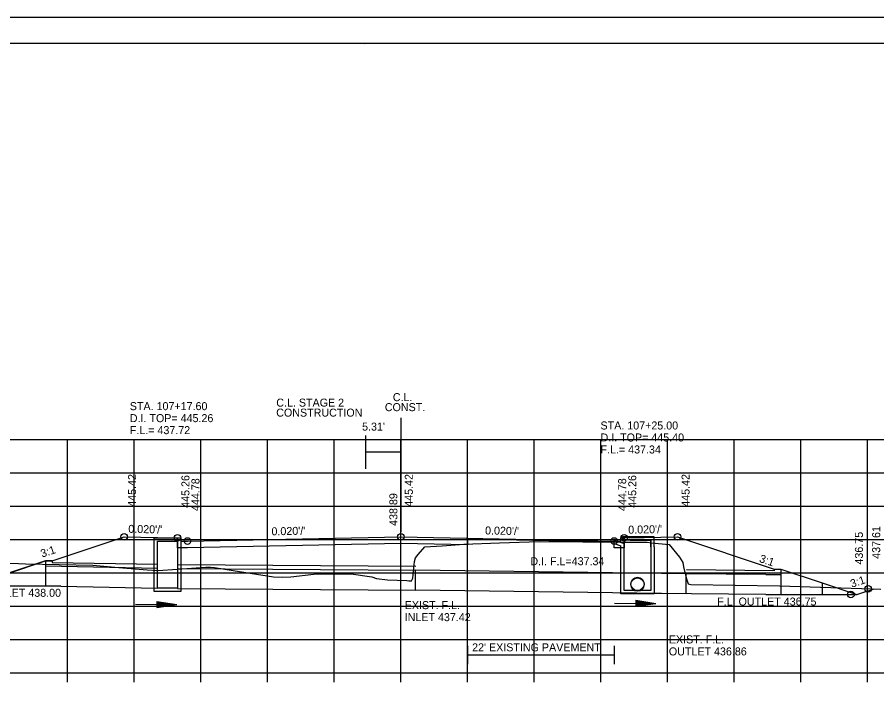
# Model space of a CAD drawing. Extents: x 1538688 to 1540766, y 656250 to 671912.
# Drawn here: x 1538800.6 to 1538929.6, y 657517.5 to 657617.9 of the extents above; entities that cross this region are included whole.
import ezdxf

# ---------------------------------------------------------------- set-up
doc = ezdxf.new("R2010")
doc.units = 0
for name, color, linetype in [('15', 7, 'Continuous'), ('18', 7, 'Continuous'), ('20', 7, 'Continuous'), ('22', 7, 'Continuous'), ('26', 7, 'Continuous'), ('39', 7, 'Continuous'), ('40', 7, 'Continuous'), ('41', 7, 'Continuous'), ('42', 7, 'Continuous'), ('7', 7, 'Continuous'), ('Borings', 7, 'Continuous'), ('Default', 7, 'Continuous'), ('RipRap', 7, 'Continuous'), ('Wall Heights', 7, 'Continuous')]:
    doc.layers.add(name, color=color, linetype=linetype)

msp = doc.modelspace()

# ---------------------------------------------------------------- linework, layer by layer
at = {"layer": '15'}
for p, q in [((1538821.58, 657530.29), (1538821.57, 657529.39)), ((1538821.57, 657530.06), (1538823.06, 657529.82)), ((1538821.58, 657530.29), (1538824.57, 657529.81)), ((1538821.58, 657530.21), (1538824.07, 657529.82)), ((1538821.58, 657530.13), (1538823.56, 657529.82)), ((1538893.42, 657530.48), (1538893.41, 657529.58)), ((1538893.42, 657530.48), (1538896.42, 657530)), ((1538893.42, 657530.4), (1538895.92, 657530.01)), ((1538893.42, 657530.33), (1538895.4, 657530.01)), ((1538893.42, 657530.25), (1538894.9, 657530.02)), ((1538893.42, 657530.17), (1538894.39, 657530.02)), ((1538893.42, 657530.1), (1538893.89, 657530.02)), ((1538821.57, 657529.98), (1538822.55, 657529.83)), ((1538821.57, 657529.91), (1538822.05, 657529.83)), ((1538821.57, 657529.69), (1538822.55, 657529.83)), ((1538821.57, 657529.77), (1538822.05, 657529.83)), ((1538821.57, 657529.54), (1538823.56, 657529.82)), ((1538821.57, 657529.46), (1538824.07, 657529.82)), ((1538821.57, 657529.61), (1538823.06, 657529.82)), ((1538821.57, 657529.39), (1538824.57, 657529.81)), ((1538893.41, 657529.73), (1538895.4, 657530.01)), ((1538893.41, 657529.65), (1538895.92, 657530.01)), ((1538893.41, 657529.58), (1538896.42, 657530)), ((1538893.42, 657529.88), (1538894.39, 657530.02)), ((1538893.42, 657529.8), (1538894.9, 657530.02)), ((1538893.42, 657529.96), (1538893.89, 657530.02))]:
    msp.add_line(p, q, dxfattribs=at)
at = {"layer": '18'}
msp.add_lwpolyline([(1538790.3, 657536.35), (1538800.84, 657535.98), (1538801.91, 657535.93), (1538811.97, 657535.71), (1538815.3, 657535.43), (1538820.11, 657535.02), (1538821.8, 657534.92), (1538827.5, 657535.34), (1538828.92, 657535.41), (1538829.61, 657535.42), (1538830.23, 657535.36), (1538833.02, 657534.94), (1538839.1, 657533.96), (1538840.37, 657533.92), (1538841.7, 657534), (1538845.15, 657534.4), (1538850.75, 657534.43), (1538853.83, 657533.98), (1538854.54, 657533.72), (1538856.17, 657533.55), (1538859.09, 657533.42), (1538859.4, 657533.38), (1538859.76, 657533.39), (1538859.96, 657533.77), (1538860.25, 657536.26), (1538860.39, 657536.85), (1538860.77, 657537.32), (1538861.8, 657538.48), (1538864.36, 657538.63), (1538867.64, 657538.88), (1538873, 657539.06), (1538878.91, 657539.3), (1538885.5, 657539.24), (1538891.24, 657539.2), (1538892, 657539.19), (1538895.14, 657539.17), (1538895.77, 657539.09), (1538898.45, 657538.84), (1538899.98, 657536.95), (1538900.49, 657536.14), (1538900.56, 657535.46), (1538900.99, 657533.83), (1538901.27, 657532.92), (1538901.69, 657532.83), (1538915, 657532.65), (1538916.53, 657532.6), (1538927.26, 657532.22), (1538930.19, 657532.13)], dxfattribs=at)
at = {"layer": '20'}
for points in [[(1538804.9, 657536.4), (1538805.9, 657536.4), (1538816.67, 657539.99), (1538821.67, 657539.89), (1538824.67, 657539.83), (1538825.17, 657539.83), (1538825.18, 657539.33), (1538826.18, 657539.35), (1538858.18, 657539.99), (1538890.18, 657539.35), (1538891.18, 657539.33), (1538891.19, 657539.83), (1538891.69, 657539.83), (1538894.69, 657539.89), (1538899.69, 657539.99), (1538914.2, 657535.15)], [(1538784.01, 657537.34), (1538793.55, 657532.57), (1538804.9, 657536.4)], [(1538921.37, 657533.06), (1538926.6, 657531.32), (1538929.19, 657532.18)]]:
    msp.add_lwpolyline(points, dxfattribs=at)
at = {"layer": '22'}
for p, q in [((1538718.18, 657554.57), (1538998.18, 657554.57)), ((1538808.18, 657519.57), (1538808.18, 657554.57)), ((1538818.18, 657519.57), (1538818.18, 657554.57)), ((1538828.18, 657519.57), (1538828.18, 657554.57)), ((1538838.18, 657519.57), (1538838.18, 657554.57)), ((1538848.18, 657519.57), (1538848.18, 657554.57)), ((1538858.18, 657519.57), (1538858.18, 657554.57)), ((1538868.18, 657519.57), (1538868.18, 657554.57)), ((1538878.18, 657519.57), (1538878.18, 657554.57)), ((1538888.18, 657519.57), (1538888.18, 657554.57)), ((1538898.18, 657519.57), (1538898.18, 657554.57)), ((1538908.18, 657519.57), (1538908.18, 657554.57)), ((1538918.18, 657519.57), (1538918.18, 657554.57)), ((1538928.18, 657519.57), (1538928.18, 657554.57)), ((1538718.18, 657549.57), (1538998.18, 657549.57)), ((1538718.18, 657544.57), (1538998.18, 657544.57)), ((1538718.18, 657539.57), (1538998.18, 657539.57)), ((1538718.18, 657534.57), (1538998.18, 657534.57)), ((1538718.18, 657529.57), (1538998.18, 657529.57)), ((1538718.18, 657524.57), (1538998.18, 657524.57)), ((1538718.18, 657519.57), (1538998.18, 657519.57))]:
    msp.add_line(p, q, dxfattribs=at)
at = {"layer": '26'}
msp.add_line((1538687.78, 657617.92), (1539021.11, 657617.92), dxfattribs=at)
msp.add_lwpolyline([(1538687.77, 657617.92), (1539021.11, 657617.92), (1539021.11, 657404.59), (1538687.77, 657404.59)], close=True, dxfattribs=at)
for centre in [(1538816.67, 657539.99), (1538858.18, 657539.99), (1538899.69, 657539.99), (1538824.67, 657539.83), (1538826.18, 657539.35), (1538826.18, 657539.35), (1538890.18, 657539.35), (1538890.18, 657539.35), (1538891.69, 657539.83), (1538928.28, 657532.18), (1538925.69, 657531.32)]:
    msp.add_circle(centre, 0.5, dxfattribs=at)
at = {"layer": '39'}
for p, q in [((1538890.18, 657539.49), (1538891.68, 657538.97)), ((1538891.34, 657539.81), (1538891.43, 657539.97)), ((1538891.34, 657539.81), (1538891.68, 657539.47)), ((1538896.18, 657539.97), (1538891.43, 657539.97)), ((1538895.68, 657539.47), (1538891.68, 657539.47)), ((1538895.68, 657538.47), (1538895.68, 657539.47)), ((1538896.18, 657538.47), (1538896.18, 657539.97)), ((1538890.18, 657538.96), (1538891.18, 657538.61)), ((1538891.18, 657538.47), (1538891.18, 657538.61)), ((1538891.68, 657538.47), (1538891.68, 657538.97)), ((1538804.9, 657536.4), (1538798.73, 657534.34)), ((1538805.9, 657536.4), (1538804.9, 657536.4)), ((1538804.9, 657536.4), (1538804.9, 657532.57)), ((1538804.9, 657535.61), (1538821.68, 657535.3)), ((1538805.9, 657536.4), (1538805.9, 657536.15)), ((1538805.9, 657536.15), (1538821.68, 657535.89)), ((1538824.68, 657535.83), (1538860.43, 657535.57)), ((1538824.68, 657535.25), (1538860.42, 657534.99)), ((1538860.4, 657531.99), (1538860.4, 657534.99)), ((1538900.99, 657534.43), (1538860.4, 657534.99)), ((1538900.99, 657531.43), (1538900.99, 657534.43)), ((1538912.94, 657534.32), (1538900.99, 657534.42)), ((1538914.2, 657534.9), (1538901.03, 657535.01)), ((1538912.94, 657534.32), (1538915.2, 657534.32)), ((1538914.2, 657535.15), (1538915.2, 657535.15)), ((1538914.2, 657535.15), (1538914.2, 657534.9)), ((1538915.2, 657535.15), (1538915.2, 657531.32)), ((1538915.2, 657535.15), (1538921.37, 657533.09)), ((1538921.37, 657533.09), (1538921.37, 657531.32)), ((1538807.16, 657532.57), (1538793.55, 657532.57)), ((1538807.16, 657532.57), (1538821.68, 657532.3)), ((1538824.67, 657532.25), (1538860.42, 657531.99)), ((1538900.99, 657531.43), (1538860.4, 657531.99)), ((1538912.94, 657531.32), (1538896.17, 657531.5)), ((1538890.23, 657530.05), (1538896.42, 657530)), ((1538912.94, 657531.32), (1538926.58, 657531.32)), ((1538818.39, 657529.86), (1538824.57, 657529.81))]:
    msp.add_line(p, q, dxfattribs=at)
for points in [[(1538823.18, 657539.83), (1538825.18, 657539.83), (1538825.18, 657531.79), (1538823.18, 657531.79), (1538821.18, 657531.79), (1538821.18, 657539.83)], [(1538823.18, 657539.33), (1538824.68, 657539.33), (1538824.68, 657532.29), (1538823.18, 657532.29), (1538821.68, 657532.29), (1538821.68, 657539.33)]]:
    msp.add_lwpolyline(points, close=True, dxfattribs=at)
for points in [[(1538890.18, 657538.96), (1538890.18, 657539.49)], [(1538892.56, 657539.47), (1538893.68, 657539.47), (1538895.68, 657539.47), (1538895.68, 657531.91), (1538893.68, 657531.91), (1538891.68, 657531.91), (1538891.68, 657537.67)], [(1538891.18, 657534.97), (1538891.18, 657538.47)], [(1538891.68, 657534.39), (1538891.68, 657538.47)], [(1538895.68, 657537.91), (1538895.68, 657534.38)], [(1538896.18, 657538.47), (1538896.18, 657534.96)], [(1538896.18, 657536.12), (1538896.18, 657531.41), (1538891.18, 657531.41), (1538891.18, 657536.46)]]:
    msp.add_lwpolyline(points, dxfattribs=at)
for centre in [(1538893.68, 657532.91), (1538893.68, 657532.91), (1538893.68, 657532.82)]:
    msp.add_circle(centre, 1, dxfattribs=at)
at = {"layer": '7'}
for p, q in [((1538868.17, 657523.61), (1538868.17, 657520.86)), ((1538890.17, 657523.61), (1538890.17, 657520.86)), ((1538890.17, 657522.24), (1538868.17, 657522.24))]:
    msp.add_line(p, q, dxfattribs=at)
at = {"layer": 'Borings'}
for p, q in [((1538718.18, 657519.57), (1538998.18, 657519.57)), ((1538808.18, 657518.17), (1538808.18, 657519.57)), ((1538818.18, 657518.17), (1538818.18, 657519.57)), ((1538828.18, 657518.17), (1538828.18, 657519.57)), ((1538838.18, 657518.17), (1538838.18, 657519.57)), ((1538848.18, 657518.17), (1538848.18, 657519.57)), ((1538858.18, 657518.17), (1538858.18, 657519.57)), ((1538868.18, 657518.17), (1538868.18, 657519.57)), ((1538878.18, 657518.17), (1538878.18, 657519.57)), ((1538888.18, 657518.17), (1538888.18, 657519.57)), ((1538898.18, 657518.17), (1538898.18, 657519.57)), ((1538908.18, 657518.17), (1538908.18, 657519.57)), ((1538918.18, 657518.17), (1538918.18, 657519.57)), ((1538928.18, 657518.17), (1538928.18, 657519.57))]:
    msp.add_line(p, q, dxfattribs=at)
at = {"layer": 'Default'}
for p, q in [((1538858.18, 657557.85), (1538858.18, 657540.73)), ((1538852.87, 657555.17), (1538852.87, 657550.17)), ((1538858.18, 657552.67), (1538852.87, 657552.67))]:
    msp.add_line(p, q, dxfattribs=at)
at = {"layer": 'RipRap'}
for p, q in [((1538700.18, 657614.03), (1539016.36, 657614.03)), ((1538852.7, 657613.77), (1538852.7, 657613.77)), ((1538852.7, 657613.77), (1538852.7, 657613.77))]:
    msp.add_line(p, q, dxfattribs=at)
at = {"layer": 'Wall Heights'}
msp.add_lwpolyline([(1538891.69, 657539.83), (1538891.69, 657538.33), (1538890.18, 657538.35), (1538890.17, 657538.35), (1538890.17, 657539.18), (1538868.17, 657539.62), (1538868.17, 657538.79), (1538858.18, 657538.99), (1538826.18, 657538.35), (1538824.67, 657538.33), (1538824.67, 657539.83)], dxfattribs=at)

# ---------------------------------------------------------------- texts
at = {"layer": '26'}
msp.add_text('+', height=0.1, dxfattribs=at).set_placement((1538823.13, 657539.78))
at = {"layer": '39'}
for s, p in [('F.L. INLET 438.00', (1538794.1, 657530.98)), ('EXIST. F.L.', (1538858.76, 657529.13)), ('F.L. OUTLET 436.75', (1538905.63, 657529.67)), ('INLET 437.42', (1538858.76, 657527.33)), ('EXIST. F.L.', (1538898.38, 657523.99)), ('OUTLET 436.86', (1538898.38, 657522.19))]:
    msp.add_text(s, height=1.2, dxfattribs=at).set_placement(p)
at = {"layer": '40'}
for s, p in [('STA. 107+17.60', (1538817.53, 657558.98)), ('D.I. TOP= 445.26', (1538817.53, 657557.18)), ('STA. 107+25.00', (1538888.13, 657556.08)), ('F.L.= 437.72', (1538817.53, 657555.38)), ('D.I. TOP= 445.40', (1538888.13, 657554.28)), ('F.L.= 437.34', (1538888.13, 657552.48)), ('D.I. F.L=437.34', (1538877.61, 657535.72))]:
    msp.add_text(s, height=1.2, dxfattribs=at).set_placement(p)
at = {"layer": '41'}
for s, p in [('445.42', (1538818.47, 657544.49)), ('445.26', (1538826.47, 657544.33)), ('444.78', (1538827.98, 657543.85)), ('445.42', (1538859.98, 657544.49)), ('444.78', (1538891.98, 657543.85)), ('445.26', (1538893.49, 657544.33)), ('445.42', (1538901.49, 657544.49)), ('438.89', (1538857.66, 657541.62)), ('436.75', (1538927.49, 657535.82)), ('437.61', (1538930.08, 657536.68))]:
    msp.add_text(s, height=1.2, rotation=90, dxfattribs=at).set_placement(p)
at = {"layer": '42'}
for s, rotation, p in [("0.020'/'", 358.8542, (1538817.3, 657540.58)), ("0.020'/'", 1.1458, (1538892.3, 657540.44)), ("0.020'/'", 1.1458, (1538838.79, 657540.2)), ("0.020'/'", 358.8542, (1538870.81, 657540.34)), ('3:1', 18.4349, (1538804.38, 657536.85)), ('3:1', 341.5651, (1538911.85, 657536.23)), ('3:1', 18.4349, (1538925.83, 657532.33))]:
    msp.add_text(s, height=1.2, rotation=rotation, dxfattribs=at).set_placement(p)
at = {"layer": '7'}
msp.add_text("22' EXISTING PAVEMENT", height=1.2, dxfattribs=at).set_placement((1538868.87, 657522.8))
at = {"layer": 'Default'}
for s, p in [('C.L.', (1538856.98, 657560.33)), ('C.L. STAGE 2', (1538839.5, 657559.51)), ('CONST.', (1538855.78, 657558.83)), ('CONSTRUCTION', (1538839.49, 657558.01)), ("5.31'", (1538852.37, 657555.91))]:
    msp.add_text(s, height=1.2, dxfattribs=at).set_placement(p)

doc.saveas('drawing.dxf')
